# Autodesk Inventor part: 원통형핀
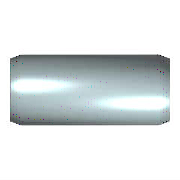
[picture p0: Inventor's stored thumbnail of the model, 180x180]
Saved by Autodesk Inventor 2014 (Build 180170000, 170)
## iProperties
IsCustomPart: 1
Created: 2012-02
Part Number: 원통형핀
Material: 강철, 연강
Description: 평행 핀
Document SubType Name: Modeling
Standard: KS B 1320
Designer: mduedu
Standards Organization: KS
Language: ko-KR
Size Designation: B 2 x  14
Categories: <MemberInstance><Categories><Category DisplayName="조임쇠" InternalName="e4da775c-781d-43d5-af7c-5136215cf5a6" Mnemonic="FSTN"><Category DisplayName="핀" InternalNa
Density: 1 g/cm^3
Appearance: 파란색 - 벽 페인트 - 광택
Author: mduedu
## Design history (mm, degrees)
sketch "스케치"
  geometry: C1 r 1 at (0, 0); 1 further point
  constraints: 1 centre point, 1 coincident
  dimensions: "d1" = 2 diameter of C1 (= NND)
extrude "본체" new body sketch "스케치" distance "d2" = 14 (= NLG); taper "d3" = 0 deg
chamfer "스케치2" distance "d8" = 0.35 (= PHH); stored, may be unused: angle "d9" = 15 deg (= FAWI), second distance "d12" = 0.35 (= PHH)
node "작업 평면1"
node "작업 평면2"
body "Solid1"
chamfer "모따기1" distance "d4" = 0.35 (= PHH); stored, may be unused: angle "d5" = 15 deg (= FAWI), second distance "d11" = 0.35 (= PHH)
other parameters: "NND" = 2 [user parameter; used in 1 equation term], "NLG" = 14 [user parameter; used in 1 equation term], "PHH" = 0.35 [user parameter; used in 4 equation terms], "FAWI" = 15 deg [user parameter; used in 2 equation terms], "d13" = 0, "d15" = 0, "d16" = 0, "KAH" = 0.25 [user parameter]
